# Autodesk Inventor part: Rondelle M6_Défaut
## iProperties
Shininess: 64.0
Length Units: 11269
Angle Units: 11279
Time Units: 11290
Mass Units: 11283
Length Display Precision: 3
Angle Display Precision: 2
Compacted: True
Part Number: Rondelle M6_Défaut
Document SubType Name: Modeling
Created: 2006-01
Material: Par défaut
Designer: Fricot
Density: 0.0
Volumn: 0.0
Area: 0.0
PropertySet Name: Model Information
Control State: 0
Master: False
Checked Out: False
Author: Fricot
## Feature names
1. Base1
